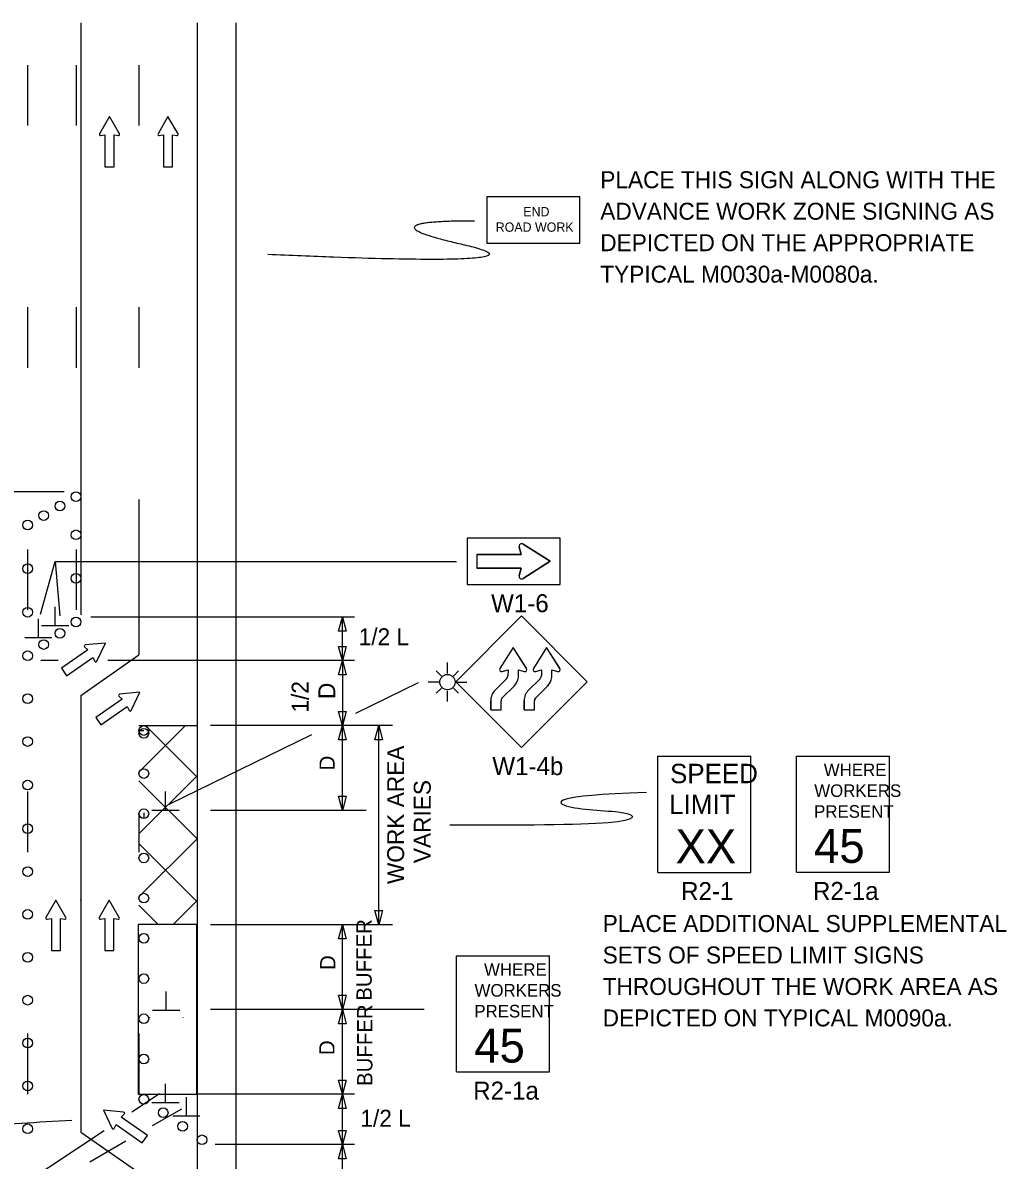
# Model space of a CAD drawing. Extents: x 16577 to 18475, y 5712 to 6909.
# Drawn here: x 16970.7 to 17376.9, y 6431.6 to 6901.4 of the extents above; entities that cross this region are included whole.
import ezdxf

# ---------------------------------------------------------------- set-up
doc = ezdxf.new("R2010")
doc.units = 0
for name, color, linetype in [('ALI_LEGAL_EX', 7, 'Continuous'), ('MT_SCRATCH_LEVEL_A', 7, 'Continuous'), ('MT_SCRATCH_LEVEL_E', 7, 'Continuous'), ('PAVT_EDGE_EX', 7, 'Continuous'), ('TRAFFIC_SIGNS_PR', 7, 'Continuous'), ('TYPICAL_TEXT_DIMEN_PR', 7, 'Continuous')]:
    doc.layers.add(name, color=color, linetype=linetype)

msp = doc.modelspace()

# ---------------------------------------------------------------- linework, layer by layer
at = {"layer": 'ALI_LEGAL_EX'}
for points in [[(16972.75, 6883.94), (16972.75, 6858.94)], [(16992.75, 6883.94), (16992.75, 6858.94)], [(17018.75, 6883.94), (17018.75, 6858.94)], [(16972.75, 6783.94), (16972.75, 6758.94)], [(16992.75, 6783.94), (16992.75, 6758.94)], [(17018.75, 6783.94), (17018.75, 6758.94)], [(16972.75, 6683.94), (16972.75, 6658.94)], [(16992.75, 6683.94), (16992.75, 6658.94)], [(17018.75, 6683.94), (17018.75, 6659.28)], [(16972.75, 6583.94), (16972.75, 6558.94)], [(17018.75, 6575.12), (17018.75, 6558.94)], [(17020.75, 6575.12), (17020.75, 6573.12)], [(16972.75, 6483.94), (16972.75, 6458.94)], [(17018.75, 6483.94), (17018.75, 6458.94)]]:
    msp.add_lwpolyline(points, dxfattribs=at)
at = {"layer": 'MT_SCRATCH_LEVEL_A'}
for p, q in [((17018.75, 6611.12), (17042.75, 6611.12)), ((17018.75, 6591.85), (17038.01, 6611.12)), ((17042.75, 6589.86), (17021.49, 6611.12)), ((17018.75, 6609.12), (17020.75, 6609.12)), ((17018.75, 6566.4), (17042.75, 6590.4)), ((17042.75, 6564.4), (17018.75, 6588.4)), ((17018.75, 6540.4), (17042.75, 6564.4)), ((17042.75, 6538.4), (17018.75, 6562.4)), ((17026.67, 6529.03), (17018.75, 6536.95)), ((17032.83, 6529.03), (17042.75, 6538.94)), ((17023.23, 6490.59), (17023.28, 6490.7)), ((17037, 6490.59), (17037.05, 6490.7))]:
    msp.add_line(p, q, dxfattribs=at)
at = {"layer": 'MT_SCRATCH_LEVEL_E'}
for p, q in [((17006.56, 6862.73), (17002.45, 6855.49)), ((17006.56, 6862.73), (17002.45, 6855.49)), ((17010.71, 6855.49), (17006.56, 6862.73)), ((17010.71, 6855.49), (17006.56, 6862.73)), ((17030.73, 6862.73), (17026.62, 6855.49)), ((17030.73, 6862.73), (17026.62, 6855.49)), ((17034.88, 6855.49), (17030.73, 6862.73)), ((17034.88, 6855.49), (17030.73, 6862.73)), ((17002.93, 6854.81), (17004.71, 6855.12)), ((17002.93, 6854.81), (17004.71, 6855.12)), ((17004.71, 6855.12), (17004.71, 6841.87)), ((17004.71, 6855.12), (17004.71, 6841.87)), ((17008.45, 6841.87), (17008.45, 6855.12)), ((17008.45, 6855.12), (17010.23, 6854.81)), ((17008.45, 6841.87), (17008.45, 6855.12)), ((17008.45, 6855.12), (17010.23, 6854.81)), ((17027.1, 6854.81), (17028.88, 6855.12)), ((17027.1, 6854.81), (17028.88, 6855.12)), ((17028.88, 6855.12), (17028.88, 6841.87)), ((17028.88, 6855.12), (17028.88, 6841.87)), ((17032.62, 6841.87), (17032.62, 6855.12)), ((17032.62, 6855.12), (17034.4, 6854.81)), ((17032.62, 6841.87), (17032.62, 6855.12)), ((17032.62, 6855.12), (17034.4, 6854.81)), ((17004.71, 6841.87), (17008.45, 6841.87)), ((17004.71, 6841.87), (17008.45, 6841.87)), ((17028.88, 6841.87), (17032.62, 6841.87)), ((17028.88, 6841.87), (17032.62, 6841.87)), ((16996.28, 6643.67), (16997.56, 6642.4)), ((16996.28, 6643.67), (16997.56, 6642.4)), ((17004.86, 6645.23), (16996.57, 6644.46)), ((17004.86, 6645.23), (16996.57, 6644.46)), ((17001.3, 6637.69), (17004.86, 6645.23)), ((17001.3, 6637.69), (17004.86, 6645.23)), ((16997.56, 6642.4), (16986.69, 6634.8)), ((16997.56, 6642.4), (16986.69, 6634.8)), ((16988.83, 6631.74), (16999.7, 6639.33)), ((16988.83, 6631.74), (16999.7, 6639.33)), ((16999.7, 6639.33), (17000.46, 6637.69)), ((16999.7, 6639.33), (17000.46, 6637.69)), ((16986.69, 6634.8), (16988.83, 6631.74)), ((16986.69, 6634.8), (16988.83, 6631.74)), ((17019.05, 6624.91), (17010.76, 6624.14)), ((17019.05, 6624.91), (17010.76, 6624.14)), ((17015.49, 6617.37), (17019.05, 6624.91)), ((17015.49, 6617.37), (17019.05, 6624.91)), ((17011.75, 6622.07), (17000.89, 6614.48)), ((17011.75, 6622.07), (17000.89, 6614.48)), ((17010.48, 6623.35), (17011.75, 6622.07)), ((17010.48, 6623.35), (17011.75, 6622.07)), ((17003.03, 6611.41), (17013.9, 6619.01)), ((17003.03, 6611.41), (17013.9, 6619.01)), ((17013.9, 6619.01), (17014.66, 6617.37)), ((17013.9, 6619.01), (17014.66, 6617.37)), ((17000.89, 6614.48), (17003.03, 6611.41)), ((17000.89, 6614.48), (17003.03, 6611.41)), ((16984.43, 6539.11), (16980.32, 6531.87)), ((16984.43, 6539.11), (16980.32, 6531.87)), ((16988.58, 6531.87), (16984.43, 6539.11)), ((16988.58, 6531.87), (16984.43, 6539.11)), ((17006.47, 6539.11), (17002.36, 6531.87)), ((17006.47, 6539.11), (17002.36, 6531.87)), ((17010.61, 6531.87), (17006.47, 6539.11)), ((17010.61, 6531.87), (17006.47, 6539.11)), ((16980.8, 6531.18), (16982.58, 6531.5)), ((16980.8, 6531.18), (16982.58, 6531.5)), ((16982.58, 6531.5), (16982.58, 6518.24)), ((16982.58, 6531.5), (16982.58, 6518.24)), ((16986.32, 6518.24), (16986.32, 6531.5)), ((16986.32, 6531.5), (16988.1, 6531.18)), ((16986.32, 6518.24), (16986.32, 6531.5)), ((16986.32, 6531.5), (16988.1, 6531.18)), ((17002.84, 6531.18), (17004.62, 6531.5)), ((17002.84, 6531.18), (17004.62, 6531.5)), ((17004.62, 6531.5), (17004.62, 6518.24)), ((17004.62, 6531.5), (17004.62, 6518.24)), ((17008.36, 6518.24), (17008.36, 6531.5)), ((17008.36, 6531.5), (17010.13, 6531.18)), ((17008.36, 6518.24), (17008.36, 6531.5)), ((17008.36, 6531.5), (17010.13, 6531.18)), ((16982.58, 6518.24), (16986.32, 6518.24)), ((16982.58, 6518.24), (16986.32, 6518.24)), ((17004.62, 6518.24), (17008.36, 6518.24)), ((17004.62, 6518.24), (17008.36, 6518.24)), ((17004.08, 6452.25), (17007.66, 6444.74)), ((17012.39, 6451.51), (17004.08, 6452.25)), ((17004.08, 6452.25), (17007.66, 6444.74)), ((17012.39, 6451.51), (17004.08, 6452.25)), ((17011.4, 6449.45), (17012.67, 6450.72)), ((17011.4, 6449.45), (17012.67, 6450.72)), ((17008.5, 6444.74), (17009.26, 6446.38)), ((17008.5, 6444.74), (17009.26, 6446.38)), ((17009.26, 6446.38), (17020.12, 6438.79)), ((17009.26, 6446.38), (17020.12, 6438.79)), ((17022.27, 6441.86), (17011.4, 6449.45)), ((17022.27, 6441.86), (17011.4, 6449.45)), ((17020.12, 6438.79), (17022.27, 6441.86)), ((17020.12, 6438.79), (17022.27, 6441.86))]:
    msp.add_line(p, q, dxfattribs=at)
for centre, start, end in [((17002.86, 6855.27), 150.4248, 279.9638), ((17002.86, 6855.27), 150.4248, 279.9638), ((17010.3, 6855.27), 260.0362, 29.7731), ((17010.3, 6855.27), 260.0362, 29.7731), ((17027.03, 6855.27), 150.4248, 279.9638), ((17027.03, 6855.27), 150.4248, 279.9638), ((17034.47, 6855.27), 260.0362, 29.7731), ((17034.47, 6855.27), 260.0362, 29.7731), ((16996.62, 6644), 95.3561, 224.895), ((16996.62, 6644), 95.3561, 224.895), ((17000.88, 6637.9), 204.9674, 334.7043), ((17000.88, 6637.9), 204.9674, 334.7043), ((17010.81, 6623.67), 95.3561, 224.895), ((17010.81, 6623.67), 95.3561, 224.895), ((17015.07, 6617.57), 204.9674, 334.7043), ((17015.07, 6617.57), 204.9674, 334.7043), ((16980.73, 6531.64), 150.4248, 279.9638), ((16980.73, 6531.64), 150.4248, 279.9638), ((16988.17, 6531.64), 260.0362, 29.7731), ((16988.17, 6531.64), 260.0362, 29.7731), ((17002.76, 6531.64), 150.4248, 279.9638), ((17002.76, 6531.64), 150.4248, 279.9638), ((17010.2, 6531.64), 260.0362, 29.7731), ((17010.2, 6531.64), 260.0362, 29.7731), ((17012.34, 6451.04), 315.105, 84.8419), ((17012.34, 6451.04), 315.105, 84.8419), ((17008.08, 6444.94), 205.4936, 335.0326), ((17008.08, 6444.94), 205.4936, 335.0326)]:
    msp.add_arc(centre, 0.463, start, end, dxfattribs=at)
at = {"layer": 'PAVT_EDGE_EX'}
for p, q in [((16994.75, 6901.43), (16994.75, 6656.96)), ((17042.75, 6901.43), (17042.75, 6139.45)), ((17058.75, 6901.43), (17058.75, 6139.45)), ((17018.75, 6704.47), (17018.75, 6640.39)), ((16994.75, 6623.63), (17018.75, 6640.39)), ((16994.75, 6623.63), (16994.75, 6618.4)), ((16994.75, 6618.4), (16994.75, 6443.28)), ((16994.75, 6539.11), (16994.75, 6539.36)), ((16994.75, 6443.28), (17018.75, 6426.52))]:
    msp.add_line(p, q, dxfattribs=at)
msp.add_lwpolyline([(17042.6, 6529.03), (17018.37, 6529.03), (17018.37, 6458.89), (17042.6, 6458.89)], close=True, dxfattribs=at)
at = {"layer": 'TRAFFIC_SIGNS_PR'}
for p, q in [((17177.46, 6686.11), (17188.62, 6679.01)), ((17158.22, 6681.81), (17176.62, 6681.81)), ((17158.22, 6681.81), (17158.22, 6676.21)), ((17176.62, 6681.81), (17175.78, 6684.87)), ((17176.62, 6676.21), (17158.22, 6676.21)), ((17175.78, 6673.15), (17176.62, 6676.21)), ((17188.62, 6679.01), (17177.46, 6671.91)), ((17176.73, 6656.42), (17149.57, 6629.27)), ((17203.88, 6629.27), (17176.73, 6656.42)), ((17143.62, 6631.62), (17141.52, 6633.73)), ((17146.14, 6632.66), (17146.14, 6637.16)), ((17148.65, 6631.62), (17150.76, 6633.73)), ((17142.98, 6629.11), (17138.15, 6629.11)), ((17149.29, 6629.11), (17154.17, 6629.11)), ((17149.57, 6629.27), (17176.73, 6602.12)), ((17165.86, 6625.81), (17170.57, 6630.52)), ((17170.57, 6630.52), (17165.86, 6625.81)), ((17176.73, 6602.12), (17203.88, 6629.27)), ((17179.66, 6625.81), (17184.37, 6630.52)), ((17184.37, 6630.52), (17179.66, 6625.81)), ((17143.62, 6626.59), (17141.52, 6624.48)), ((17146.14, 6621.14), (17146.14, 6625.55)), ((17148.65, 6626.59), (17150.76, 6624.49)), ((17168.91, 6622.75), (17173.63, 6627.47)), ((17168.91, 6622.75), (17173.63, 6627.47)), ((17182.71, 6622.75), (17187.42, 6627.47)), ((17182.71, 6622.75), (17187.42, 6627.47)), ((17163.99, 6617.69), (17163.99, 6621.39)), ((17168.31, 6617.69), (17168.31, 6621.39)), ((17177.79, 6617.69), (17177.79, 6621.39)), ((17182.11, 6617.69), (17182.11, 6621.39)), ((17163.99, 6617.69), (17168.31, 6617.69)), ((17177.79, 6617.69), (17182.11, 6617.69)), ((17233.03, 6598.51), (17271.43, 6598.51)), ((17233.03, 6550.51), (17233.03, 6598.51)), ((17271.43, 6550.51), (17271.43, 6598.51)), ((17290.23, 6598.59), (17328.63, 6598.59)), ((17290.23, 6550.59), (17290.23, 6598.59)), ((17328.63, 6550.59), (17328.63, 6598.59)), ((17233.03, 6550.51), (17271.43, 6550.51)), ((17290.23, 6550.59), (17328.63, 6550.59)), ((17149.93, 6516.12), (17188.33, 6516.12)), ((17149.93, 6468.12), (17149.93, 6516.12)), ((17188.33, 6468.12), (17188.33, 6516.12)), ((17149.93, 6468.12), (17188.33, 6468.12))]:
    msp.add_line(p, q, dxfattribs=at)
for points in [[(17162.45, 6810.36), (17200.85, 6810.36), (17200.85, 6829.56), (17162.45, 6829.56)], [(17154.22, 6669.41), (17192.62, 6669.41), (17192.62, 6688.61), (17154.22, 6688.61)]]:
    msp.add_lwpolyline(points, close=True, dxfattribs=at)
for points in [[(17177.46, 6671.91), (17188.62, 6679.01), (17177.46, 6686.11)], [(17175.78, 6684.87), (17176.62, 6681.81), (17158.22, 6681.81), (17158.22, 6676.21), (17176.62, 6676.21), (17175.78, 6673.15)], [(17178.78, 6634.8), (17173.3, 6643.41), (17167.82, 6634.79)], [(17178.78, 6634.79), (17173.3, 6643.41), (17167.82, 6634.79)], [(17192.58, 6634.8), (17187.09, 6643.41), (17181.61, 6634.79)], [(17192.58, 6634.79), (17187.09, 6643.41), (17181.61, 6634.79)], [(17168.78, 6633.5), (17171.14, 6634.15), (17171.13, 6631.85)], [(17168.78, 6633.5), (17169.61, 6633.73), (17171.14, 6634.15), (17171.13, 6631.85)], [(17175.45, 6631.78), (17175.45, 6634.15), (17177.82, 6633.5)], [(17175.45, 6631.78), (17175.45, 6634.15), (17177.82, 6633.5)], [(17182.57, 6633.5), (17184.93, 6634.15), (17184.93, 6631.85)], [(17182.57, 6633.5), (17183.41, 6633.73), (17184.93, 6634.15), (17184.93, 6631.85)], [(17189.25, 6631.78), (17189.25, 6634.15), (17191.62, 6633.5)], [(17189.25, 6631.78), (17189.25, 6634.15), (17191.62, 6633.5)], [(17163.99, 6621.39), (17163.99, 6617.69), (17168.31, 6617.69), (17168.31, 6621.39)], [(17177.79, 6621.39), (17177.79, 6617.69), (17182.11, 6617.69), (17182.11, 6621.39)]]:
    msp.add_lwpolyline(points, dxfattribs=at)
for centre, radius in [((16992.75, 6705.73), 2), ((16979.42, 6697.9), 2), ((16986.08, 6701.82), 2), ((16972.75, 6693.98), 2), ((16992.75, 6689.95), 2), ((16972.75, 6675.98), 2), ((16992.75, 6671.95), 2), ((16972.75, 6657.98), 2), ((16992.75, 6653.95), 2), ((16986.08, 6649.29), 2), ((16979.42, 6644.63), 2), ((16972.75, 6639.98), 2), ((16972.75, 6639.98), 2), ((17146.14, 6629.11), 3.15), ((16972.75, 6622.27), 2), ((17020.75, 6609.12), 2), ((16972.75, 6604.57), 2), ((17020.75, 6607.96), 2), ((17020.75, 6591.35), 2), ((16972.75, 6586.57), 2), ((17020.75, 6574.73), 2), ((16972.75, 6568.57), 2), ((17020.75, 6556.51), 2), ((16972.75, 6550.86), 2), ((17020.75, 6539.89), 2), ((16972.75, 6533.16), 2), ((17020.75, 6523.28), 2), ((16972.75, 6515.45), 2), ((17020.75, 6506.67), 2), ((16972.75, 6497.75), 2), ((17020.75, 6490.06), 2), ((16972.75, 6480.04), 2), ((17020.75, 6473.44), 2), ((16972.75, 6462.34), 2), ((17020.75, 6456.83), 2), ((17028.75, 6451.25), 2), ((16972.75, 6444.63), 2), ((17036.75, 6445.66), 2), ((17044.75, 6440.07), 2)]:
    msp.add_circle(centre, radius, dxfattribs=at)
for centre, radius, start, end in [((17176.86, 6685.16), 1.12, 57.5304, 195.3269), ((17176.86, 6685.16), 1.12, 57.5304, 195.3269), ((17176.86, 6672.85), 1.12, 164.6731, 302.4696), ((17176.86, 6672.85), 1.12, 164.6731, 302.4696), ((17168.55, 6634.33), 0.866, 147.5288, 285.3852), ((17168.55, 6634.33), 0.864, 147.5204, 285.3986), ((17178.05, 6634.33), 0.866, 254.6828, 32.2708), ((17178.05, 6634.33), 0.866, 254.6799, 32.2804), ((17187.89, 6640.59), 10.8, 212.4569, 212.4665), ((17182.34, 6634.33), 0.866, 147.5288, 285.3852), ((17182.34, 6634.33), 0.864, 147.5204, 285.3986), ((17191.84, 6634.33), 0.866, 254.6828, 32.2708), ((17191.84, 6634.33), 0.866, 254.6799, 32.2804), ((17201.69, 6640.59), 10.8, 212.4569, 212.4665), ((17169.28, 6631.85), 1.85, 314.2125, 0), ((17169.28, 6631.85), 1.85, 314.2123, 0.1238), ((17169.28, 6631.85), 6.17, 314.2125, 359.3819), ((17169.28, 6631.85), 6.17, 314.7687, 359.3755), ((17174.97, 6623.08), 10.8, 74.68, 74.6808), ((17183.08, 6631.85), 1.85, 314.2125, 0), ((17183.08, 6631.85), 1.85, 314.2123, 0.1238), ((17183.08, 6631.85), 6.17, 314.2125, 359.3819), ((17183.08, 6631.85), 6.17, 314.7687, 359.3755), ((17188.76, 6623.08), 10.8, 74.68, 74.6808), ((17170.16, 6621.39), 6.17, 134.2125, 180), ((17170.16, 6621.39), 6.17, 134.2125, 180), ((17170.16, 6621.39), 6.17, 134.2117, 180), ((17183.96, 6621.39), 6.17, 134.2125, 180), ((17183.96, 6621.39), 6.17, 134.2125, 180), ((17183.96, 6621.39), 6.17, 134.2117, 180), ((17170.16, 6621.39), 1.85, 132.372, 180), ((17170.16, 6621.39), 1.85, 134.2125, 180), ((17183.96, 6621.39), 1.85, 132.372, 180), ((17183.96, 6621.39), 1.85, 134.2125, 180)]:
    msp.add_arc(centre, radius, start, end, dxfattribs=at)
msp.add_open_spline([(17157.27, 6819.54), (17110.03, 6819.54), (17195.05, 6800.19), (17071.96, 6805.68)], degree=2, dxfattribs=at)
at = {"layer": 'TYPICAL_TEXT_DIMEN_PR'}
for p, q in [((16987.84, 6707.73), (16857.65, 6707.73)), ((16978.07, 6657.21), (16984.12, 6678.99)), ((16984.12, 6678.99), (17149.87, 6678.99)), ((16984.12, 6678.99), (16986.11, 6656.47)), ((16984.12, 6652.38), (16984.12, 6660.17)), ((16977.2, 6647.43), (16977.2, 6655.22)), ((16989.75, 6652.38), (16978.5, 6652.38)), ((17107.75, 6655.95), (16998.81, 6655.95)), ((17101.18, 6650.08), (17102.75, 6655.95)), ((17102.75, 6637.98), (17102.75, 6655.95)), ((17102.75, 6655.95), (17104.32, 6650.08)), ((17102.75, 6650.08), (17101.18, 6650.08)), ((17104.32, 6650.08), (17102.75, 6650.08)), ((16982.82, 6647.43), (16971.57, 6647.43)), ((17102.75, 6637.98), (17101.18, 6643.84)), ((17101.18, 6643.84), (17102.75, 6643.84)), ((17102.75, 6643.84), (17104.32, 6643.84)), ((17104.32, 6643.84), (17102.75, 6637.98)), ((16985.38, 6637.98), (16978.19, 6637.98)), ((17107.75, 6637.98), (17005.82, 6637.98)), ((17101.18, 6632.12), (17102.75, 6637.98)), ((17102.75, 6637.98), (17104.32, 6632.12)), ((17102.75, 6637.98), (17102.75, 6611.12)), ((17102.75, 6632.12), (17101.18, 6632.12)), ((17104.32, 6632.12), (17102.75, 6632.12)), ((17134.11, 6628.84), (17108.16, 6616.17)), ((17102.75, 6611.12), (17101.18, 6616.98)), ((17101.18, 6616.98), (17102.75, 6616.98)), ((17102.75, 6616.98), (17104.32, 6616.98)), ((17104.32, 6616.98), (17102.75, 6611.12)), ((17123.47, 6611.12), (17048.25, 6611.12)), ((17101.18, 6605.26), (17102.75, 6611.12)), ((17102.75, 6576.12), (17102.75, 6611.12)), ((17102.75, 6611.12), (17104.32, 6605.26)), ((17116.18, 6605.26), (17117.75, 6611.12)), ((17117.75, 6528.89), (17117.75, 6611.12)), ((17117.75, 6611.12), (17119.32, 6605.26)), ((17090.04, 6607.31), (17031.08, 6578.52)), ((17102.75, 6605.26), (17101.18, 6605.26)), ((17104.32, 6605.26), (17102.75, 6605.26)), ((17117.75, 6605.26), (17116.18, 6605.26)), ((17119.32, 6605.26), (17117.75, 6605.26)), ((17029.72, 6576.14), (17029.72, 6583.92)), ((17102.75, 6576.12), (17101.18, 6581.98)), ((17101.18, 6581.98), (17102.75, 6581.98)), ((17102.75, 6581.98), (17104.32, 6581.98)), ((17104.32, 6581.98), (17102.75, 6576.12)), ((17035.35, 6576.14), (17024.1, 6576.14)), ((17112.51, 6576.12), (17048.25, 6576.12)), ((17117.75, 6528.89), (17116.18, 6534.75)), ((17116.18, 6534.75), (17117.75, 6534.75)), ((17117.75, 6534.75), (17119.32, 6534.75)), ((17119.32, 6534.75), (17117.75, 6528.89)), ((17123.47, 6528.89), (17048.25, 6528.89)), ((17101.18, 6523.02), (17102.75, 6528.89)), ((17102.75, 6493.89), (17102.75, 6528.89)), ((17102.75, 6528.89), (17104.32, 6523.02)), ((17102.75, 6523.02), (17101.18, 6523.02)), ((17104.32, 6523.02), (17102.75, 6523.02)), ((17029.98, 6493.52), (17029.98, 6501.31)), ((17102.75, 6493.89), (17101.18, 6499.75)), ((17101.18, 6499.75), (17102.75, 6499.75)), ((17102.75, 6499.75), (17104.32, 6499.75)), ((17104.32, 6499.75), (17102.75, 6493.89)), ((17035.61, 6493.52), (17024.36, 6493.52)), ((17136.56, 6493.89), (17048.25, 6493.89)), ((17101.18, 6488.02), (17102.75, 6493.89)), ((17102.75, 6458.89), (17102.75, 6493.89)), ((17102.75, 6493.89), (17104.32, 6488.02)), ((17102.75, 6488.02), (17101.18, 6488.02)), ((17104.32, 6488.02), (17102.75, 6488.02)), ((17102.75, 6458.89), (17101.18, 6464.75)), ((17101.18, 6464.75), (17102.75, 6464.75)), ((17102.75, 6464.75), (17104.32, 6464.75)), ((17104.32, 6464.75), (17102.75, 6458.89)), ((17029.72, 6455.38), (17029.72, 6463.17)), ((17027.27, 6459.06), (17015.85, 6451.49)), ((17035.35, 6455.38), (17024.1, 6455.38)), ((17038.32, 6449.87), (17038.32, 6457.65)), ((17107.75, 6458.89), (17042.75, 6458.89)), ((17101.18, 6453.02), (17102.75, 6458.89)), ((17102.75, 6458.89), (17104.32, 6453.02)), ((17102.75, 6438.07), (17102.75, 6458.89)), ((17024.36, 6445.93), (17036.48, 6452.92)), ((17102.75, 6453.02), (17101.18, 6453.02)), ((17104.32, 6453.02), (17102.75, 6453.02)), ((17043.94, 6449.87), (17032.69, 6449.87)), ((17004.32, 6443.85), (16894.07, 6370.79)), ((17102.75, 6438.07), (17101.18, 6443.94)), ((17101.18, 6443.94), (17102.75, 6443.94)), ((17102.75, 6443.94), (17104.32, 6443.94)), ((17104.32, 6443.94), (17102.75, 6438.07)), ((16998.42, 6430.97), (17013.38, 6439.6)), ((17107.75, 6438.07), (17050.26, 6438.07)), ((17101.18, 6432.21), (17102.75, 6438.07)), ((17102.75, 6403.07), (17102.75, 6438.07)), ((17102.75, 6438.07), (17104.32, 6432.21)), ((17102.75, 6432.21), (17101.18, 6432.21)), ((17104.32, 6432.21), (17102.75, 6432.21))]:
    msp.add_line(p, q, dxfattribs=at)
for points, degree in [([(17228.28, 6583.51), (17188.87, 6582.37), (17191.25, 6576.16), (17224.53, 6576.16), (17224.53, 6570), (17176.23, 6570), (17147.1, 6570)], 3), ([(16991.03, 6448.11), (16908.56, 6442.63), (16908.56, 6450.51), (16944.52, 6450.51), (16944.52, 6456.66), (16896.23, 6456.66), (16892.29, 6456.66)], 2)]:
    msp.add_open_spline(points, degree=degree, dxfattribs=at)

# ---------------------------------------------------------------- texts
at = {"layer": 'TRAFFIC_SIGNS_PR'}
for s, height, p in [('PLACE THIS SIGN ALONG WITH THE', 7, (17209.24, 6833.09)), ('ADVANCE WORK ZONE SIGNING AS', 7, (17209.24, 6820.09)), ('END', 3.831, (17177.46, 6821.49)), ('ROAD WORK', 3.831, (17166.06, 6815.11)), ('DEPICTED ON THE APPROPRIATE', 7, (17209.24, 6807.09)), ('TYPICAL M0030a-M0080a.', 7, (17209.24, 6794.09)), ('W1-6', 7.44, (17164.16, 6657.97)), ('W1-4b', 7.44, (17164.68, 6590.68)), ('SPEED', 8, (17238.07, 6587.37)), ('WHERE', 5.2, (17301.54, 6590.28)), ('WORKERS', 5.2, (17297.61, 6581.68)), ('LIMIT', 8, (17237.74, 6574.57)), ('PRESENT', 5.2, (17297.55, 6573.08)), ('XX', 14.031, (17240.34, 6554.26)), ('45', 14.031, (17297.54, 6554.45)), ('R2-1', 7.44, (17242.64, 6539.07)), ('R2-1a', 7.44, (17297.08, 6539.15)), ('PLACE ADDITIONAL SUPPLEMENTAL', 7, (17210.23, 6525.9)), ('SETS OF SPEED LIMIT SIGNS', 7, (17210.23, 6512.9)), ('WHERE', 5.2, (17161.24, 6507.81)), ('THROUGHOUT THE WORK AREA AS', 7, (17210.23, 6499.9)), ('WORKERS', 5.2, (17157.31, 6499.21)), ('PRESENT', 5.2, (17157.24, 6490.61)), ('DEPICTED ON TYPICAL M0090a.', 7, (17210.23, 6486.9)), ('45', 14.031, (17157.23, 6471.98)), ('R2-1a', 7.44, (17156.78, 6456.68))]:
    msp.add_text(s, height=height, dxfattribs=at).set_placement(p)
at = {"layer": 'TYPICAL_TEXT_DIMEN_PR'}
for p in [(17109.48, 6644.35), (17110.18, 6445.49)]:
    msp.add_text('1/2 L', height=7, dxfattribs=at).set_placement(p)
for s, height, p in [('1/2', 7, (17088.82, 6616.53)), ('D', 7, (17099.82, 6622.1)), ('WORK AREA', 7, (17128.24, 6545.69)), ('D', 6.3, (17099.6, 6592.62)), ('VARIES', 7, (17139.24, 6554.33)), ('BUFFER', 6.3, (17114.86, 6497.52)), ('D', 6.3, (17099.84, 6510.21)), ('BUFFER', 6.3, (17115.15, 6462.32)), ('D', 6.3, (17099.49, 6475.07))]:
    msp.add_text(s, height=height, rotation=90, dxfattribs=at).set_placement(p)

doc.saveas('drawing.dxf')
